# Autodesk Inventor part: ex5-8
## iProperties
Created: 2007-02
Part Number: ex5-8
Document SubType Name: Modeling
Designer: Elise Moss
Density: 1 g/cm^3
Author: Elise Moss
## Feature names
1. Extrusion1
2. ipod opening [Extrusion]
3. connector opening [Extrusion]
4. Fillet1
5. tab [Extrusion]
6. Hole1
7. Mirror2
8. Fillet3
